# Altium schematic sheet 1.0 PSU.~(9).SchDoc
size A4; SheetNumber: 1; SheetTotal: 7
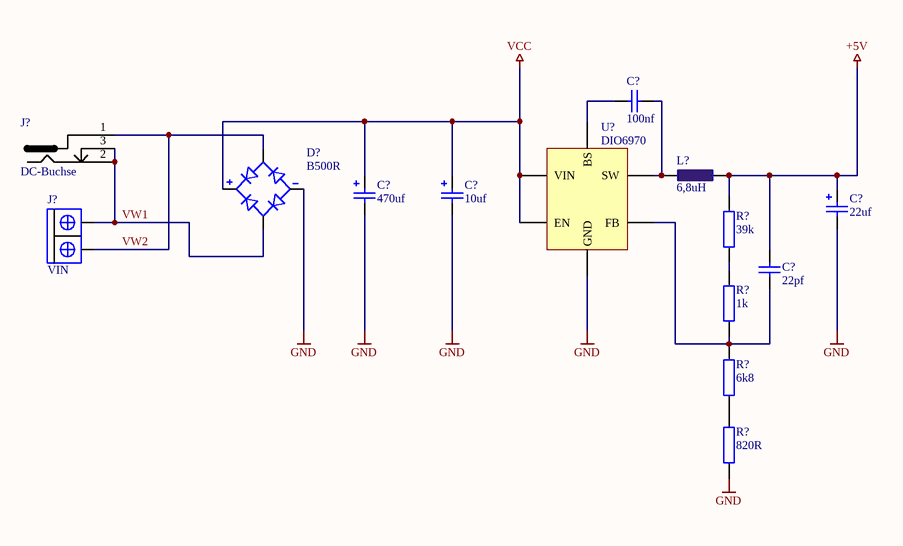
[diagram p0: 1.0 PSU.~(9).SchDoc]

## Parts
(Parts that share a designator on the sheet are numbered #1, #2 ... from top to bottom, then left to right.)
C?#1  100nf  [C_SMD_0805]
C?#2  470uf  [C_SMD_D-TYP]
C?#3  10uf  [C_SMD_C-TYP]
C?#4  22uf  [C_SMD_C-TYP]
C?#5  22pf  [C_SMD_0805]
D?  B500R  [D_THT_FBR-R]
J?#1  DC-Buchse  [J_THT_CUI_PJ-006A]
J?#2  VIN  [J_THT_Printklemme 2x]
L?  6,8uH  [L_SMD_BWVS00606045]
R?#1  39k  [R_SMD_0805]
R?#2  1k  [R_SMD_0805]
R?#3  6k8  [R_SMD_0805]
R?#4  820R  [R_SMD_0805]
U?  DIO6970  [SOT23-6]

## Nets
+5V: C?#4.1 C?#5.1 L?.1 R?#1.2
GND: C?#2.2 C?#3.2 C?#4.2 D?.4(NEG) R?#4.1 U?.1(GND)
VCC: C?#2.1 C?#3.1 D?.1(POS) U?.3(VIN) U?.5(EN)
VW1: D?.3(AC2) J?#1.2 J?#1.3 J?#2.2
VW2: D?.2(AC1) J?#1.1 J?#2.1
NetC?#1_1: C?#1.1 U?.6(BS)
NetC?#1_2: C?#1.2 L?.2 U?.2(SW)
NetC?#5_2: C?#5.2 R?#2.1 R?#3.2 U?.4(FB)
NetR?#1_1: R?#1.1 R?#2.2
NetR?#3_1: R?#3.1 R?#4.2

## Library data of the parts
C?#1 C?#5 = C_SMD_KO: Kondensator SMD Universal, Keramik, Folie, usw.
C?#2-C?#4 = C_SMD_ELK: SMD Elektrolytkondensator
D? = D_THT_Brückengleichrichter: Bruckengleichrichter
J?#1 = J_THT_Hohlstecker
J?#2 = J_THT_Printklemme 2x: Printklemme
L? = L_SMD_Spule: Spule SMD
R?#1-R?#4 = R_SMD_Widerstand: Widerstand SMD
U? = U_DIO6970: Buckconverter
